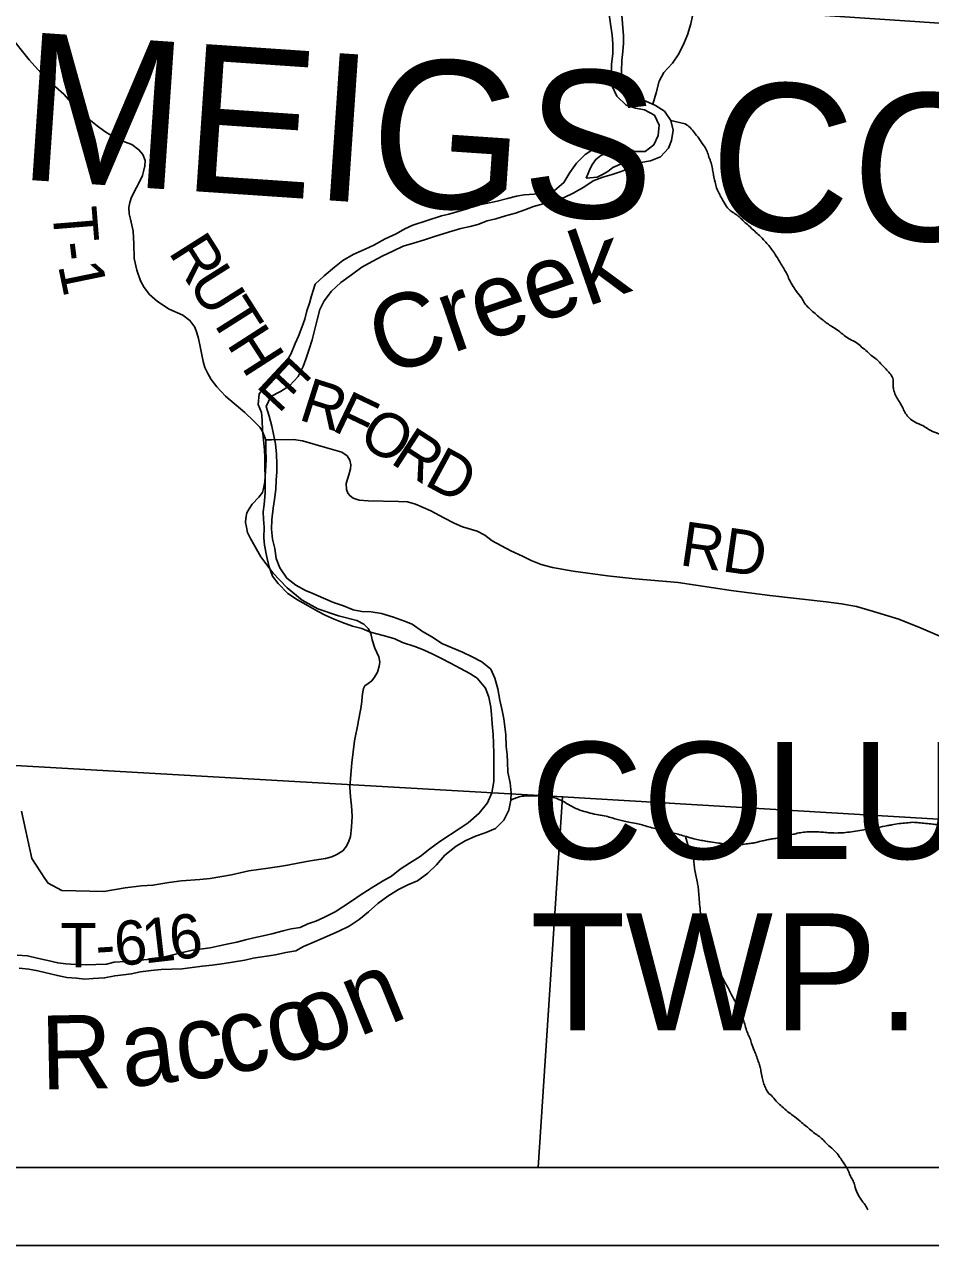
# Model space of a CAD drawing. Extents: x -8.2 to 34, y 0 to 22.
# Drawn here: x 4.523 to 5.685, y 14 to 15.567 of the extents above; entities that cross this region are included whole.
import ezdxf

# ---------------------------------------------------------------- set-up
doc = ezdxf.new("R2010")
doc.units = 0
for name, color, linetype in [('GM_X_Corporation', 7, 'Continuous'), ('GM_X_County_Text', 7, 'Continuous'), ('GM_X_Major_River', 7, 'Continuous'), ('GM_X_Major_River_Text', 7, 'Continuous'), ('GM_X_Minor_River', 7, 'Continuous'), ('GM_X_Township_Road', 7, 'Continuous'), ('GM_X_Township_Road_Text', 7, 'Continuous'), ('GM_X_Township_Text', 7, 'Continuous'), ('SH_Data', 7, 'Continuous')]:
    doc.layers.add(name, color=color, linetype=linetype)

msp = doc.modelspace()

# ---------------------------------------------------------------- linework, layer by layer
at = {"layer": 'GM_X_Corporation'}
for points in [[(4.1481, 14.1), (8.9, 14.1), (8.9, 15.3663), (8.5054, 15.392), (7.8479, 15.4343), (7.082, 15.4841), (6.7558, 15.5053), (6.7389, 15.5064), (6.2987, 15.5287), (5.4088, 15.5882), (4.4836, 15.6492), (4.4152, 15.6505), (4.2922, 15.6569), (4.2674, 15.658), (4.2558, 15.6585), (4.2352, 15.4906), (4.2113, 15.0848), (4.1846, 14.6878), (4.1741, 14.5315), (4.1604, 14.3288)], [(4.1538, 14.1), (5.1819, 14.1), (5.2132, 14.576), (4.1896, 14.6347)], [(5.1819, 14.1), (6.2054, 14.1), (6.2355, 14.5152), (5.2132, 14.576)]]:
    msp.add_lwpolyline(points, close=True, dxfattribs=at)
at = {"layer": 'GM_X_Major_River'}
for points in [[(5.272, 15.5853), (5.2766, 15.5533), (5.2778, 15.5423), (5.2778, 15.5298), (5.2759, 15.5157), (5.2756, 15.5017), (5.2768, 15.488), (5.2828, 15.4752), (5.2946, 15.4635), (5.3067, 15.4597), (5.3185, 15.4575), (5.331, 15.4507), (5.337, 15.4378), (5.3359, 15.4245), (5.3303, 15.4127), (5.319, 15.404), (5.3053, 15.4043), (5.294, 15.4104), (5.2807, 15.4141), (5.2674, 15.4141), (5.2557, 15.4091), (5.2421, 15.4004), (5.2312, 15.389), (5.2225, 15.3772), (5.2149, 15.3643), (5.2028, 15.354), (5.1904, 15.3513), (5.1767, 15.3494), (5.1639, 15.3486), (5.154, 15.3467), (5.1423, 15.3436), (5.1291, 15.3405), (5.1151, 15.3374), (5.1026, 15.3348), (5.0909, 15.3306), (5.0803, 15.3275), (5.0674, 15.3237), (5.0576, 15.3217), (5.0212, 15.3095), (5.0107, 15.3049), (4.9997, 15.2984), (4.9857, 15.292), (4.971, 15.284), (4.96, 15.2786), (4.9445, 15.2718), (4.9313, 15.2641), (4.9203, 15.2558), (4.9074, 15.2447), (4.8957, 15.2337), (4.8908, 15.2189), (4.8882, 15.2094), (4.8848, 15.1995), (4.8822, 15.1889), (4.8788, 15.1794), (4.8743, 15.1673), (4.8702, 15.1578), (4.8645, 15.1441), (4.8577, 15.1324), (4.8479, 15.1187), (4.8351, 15.1065), (4.8237, 15.0932), (4.8226, 15.0796), (4.8268, 15.0693), (4.8276, 15.0595), (4.828, 15.0466), (4.8292, 15.0337), (4.8307, 15.0212), (4.8311, 15.0113), (4.8311, 14.9988), (4.8315, 14.9863), (4.8316, 14.9659), (4.8301, 14.9511), (4.829, 14.9416), (4.8294, 14.9321), (4.8302, 14.9222), (4.8298, 14.9082), (4.8306, 14.8987), (4.8333, 14.8855), (4.8363, 14.8722), (4.8409, 14.8593), (4.8481, 14.8495), (4.8606, 14.8367), (4.8732, 14.8287), (4.8868, 14.8212), (4.8985, 14.8144), (4.9092, 14.8087), (4.9201, 14.8038), (4.9308, 14.7997), (4.9436, 14.7948), (4.9554, 14.7918), (4.9667, 14.7873), (4.9766, 14.7847), (4.9876, 14.7817), (4.9978, 14.7787), (5.0077, 14.7741), (5.0236, 14.7689), (5.0345, 14.7647), (5.0467, 14.7591), (5.0569, 14.7538), (5.0694, 14.7474)], [(5.2914, 15.5527), (5.2889, 15.5842)], [(5.1213, 14.7396), (5.1095, 14.749), (5.097, 14.7558), (5.0849, 14.7615), (5.0584, 14.7728), (5.0463, 14.7807), (5.0334, 14.7882), (5.0201, 14.7973), (5.0102, 14.8014), (4.9962, 14.8063), (4.9807, 14.8112), (4.9674, 14.8135), (4.9557, 14.8138), (4.9443, 14.8157), (4.9322, 14.8209), (4.9193, 14.8254), (4.9065, 14.8307), (4.8928, 14.8367), (4.8833, 14.8409), (4.8708, 14.8477), (4.8591, 14.8567), (4.8503, 14.87), (4.8458, 14.8817), (4.8439, 14.8946), (4.8408, 14.9067), (4.8396, 14.9196), (4.84, 14.9314), (4.8419, 14.9465), (4.8433, 14.9575), (4.8452, 14.9708), (4.8456, 14.9822), (4.8463, 14.9928), (4.8466, 15.003), (4.8459, 15.0159), (4.8447, 15.0288), (4.8401, 15.0516), (4.8367, 15.0644), (4.8329, 15.0769), (4.8389, 15.0895), (4.851, 15.0963), (4.8627, 15.1032), (4.8737, 15.1153), (4.8804, 15.1283), (4.8838, 15.1377), (4.888, 15.1506), (4.8917, 15.1624), (4.8981, 15.1882), (4.9015, 15.2015), (4.9071, 15.2125), (4.9166, 15.225), (4.9287, 15.2361), (4.9423, 15.246), (4.9555, 15.2555), (4.9687, 15.2631), (4.9823, 15.2703), (4.9963, 15.2768), (5.0088, 15.2825), (5.0217, 15.2864), (5.036, 15.2906), (5.0474, 15.2948), (5.061, 15.299), (5.0712, 15.3017), (5.0826, 15.3051), (5.0947, 15.3078), (5.1045, 15.3105), (5.1166, 15.3151), (5.1276, 15.3178), (5.1401, 15.3216), (5.1526, 15.325), (5.1647, 15.3292), (5.176, 15.3334), (5.1881, 15.3369), (5.2006, 15.3411), (5.215, 15.3453), (5.2267, 15.3507), (5.2403, 15.3583), (5.2524, 15.3663), (5.2649, 15.3712), (5.277, 15.3747), (5.2883, 15.3785), (5.3012, 15.3838), (5.3137, 15.3899), (5.3258, 15.3923), (5.3387, 15.3972), (5.3492, 15.4086), (5.353, 15.4181), (5.3549, 15.4314), (5.3522, 15.4439), (5.3438, 15.456), (5.3324, 15.4632), (5.3199, 15.4688), (5.3067, 15.4737), (5.2953, 15.4828), (5.2896, 15.4949), (5.2888, 15.5074), (5.2892, 15.5207), (5.2903, 15.5324), (5.2914, 15.5431), (5.2914, 15.5527)], [(5.2974, 15.3952), (5.2906, 15.3975), (5.2822, 15.4001), (5.2747, 15.402), (5.2686, 15.4016), (5.2622, 15.3989), (5.2558, 15.394), (5.2509, 15.3864), (5.2478, 15.3803), (5.2433, 15.37)], [(5.2433, 15.37), (5.2577, 15.3712), (5.2645, 15.3746), (5.2713, 15.3785), (5.2777, 15.3834), (5.2838, 15.3861), (5.2883, 15.3884), (5.2932, 15.3906), (5.2974, 15.3952)], [(5.0694, 14.7474), (5.0823, 14.7406), (5.094, 14.7342), (5.1035, 14.7282), (5.1142, 14.7153), (5.1187, 14.7039), (5.121, 14.6911), (5.1218, 14.6816), (5.123, 14.6695), (5.1241, 14.6558), (5.1245, 14.6448), (5.1249, 14.6312), (5.125, 14.5955), (5.1224, 14.5811), (5.1167, 14.5682), (5.1062, 14.5549), (5.0922, 14.5424), (5.0816, 14.5359), (5.0555, 14.5184), (5.0427, 14.5092), (5.0302, 14.4993), (5.0166, 14.4906), (5.0049, 14.483), (4.9935, 14.4742), (4.9822, 14.4677), (4.9675, 14.4586), (4.9535, 14.4498), (4.9436, 14.443), (4.9312, 14.4346), (4.9213, 14.4285), (4.9066, 14.4209), (4.8964, 14.4163), (4.8862, 14.4129), (4.8763, 14.4083), (4.865, 14.4064), (4.8548, 14.4041), (4.84, 14.3999), (4.829, 14.3976), (4.8169, 14.3949), (4.8063, 14.3926), (4.795, 14.3895), (4.7844, 14.3872), (4.7723, 14.3845), (4.7609, 14.3822), (4.7511, 14.381), (4.7382, 14.3791), (4.7273, 14.3764), (4.7114, 14.3726), (4.7008, 14.3703), (4.6909, 14.3687), (4.6803, 14.3672), (4.6667, 14.366), (4.6527, 14.3645), (4.6376, 14.3637), (4.6277, 14.3613), (4.6141, 14.3606), (4.6016, 14.3605), (4.5884, 14.3609), (4.5755, 14.3616), (4.5653, 14.3627), (4.5524, 14.3657), (4.5391, 14.3687), (4.5263, 14.3717), (4.5134, 14.3728)], [(4.5157, 14.3561), (4.5282, 14.3546), (4.5399, 14.3524), (4.5649, 14.3464), (4.5771, 14.3441), (4.5892, 14.343), (4.6001, 14.3419), (4.6107, 14.3427), (4.6255, 14.3435), (4.6387, 14.3462), (4.6497, 14.3474), (4.6596, 14.3486), (4.6717, 14.3512), (4.6853, 14.3532), (4.6982, 14.3543), (4.7114, 14.3548), (4.725, 14.3552), (4.7379, 14.3567), (4.7511, 14.3587), (4.7636, 14.3598), (4.7788, 14.3622), (4.792, 14.3641), (4.8053, 14.3664), (4.8159, 14.3687), (4.8446, 14.3733), (4.8579, 14.376), (4.8707, 14.3783), (4.8809, 14.3837), (4.8949, 14.3898), (4.9048, 14.394), (4.9252, 14.4031), (4.9392, 14.41), (4.952, 14.4184), (4.9641, 14.4283), (4.9762, 14.4389), (4.9891, 14.4484), (5.0027, 14.4568), (5.0144, 14.4629), (5.0272, 14.4683), (5.0401, 14.4781), (5.0514, 14.4888), (5.062, 14.501), (5.0764, 14.5124), (5.0881, 14.5196), (5.1013, 14.5253), (5.1138, 14.5299), (5.127, 14.5353), (5.1376, 14.5459), (5.1444, 14.5588), (5.1466, 14.5717), (5.147, 14.5812), (5.1458, 14.5937), (5.1428, 14.6077), (5.1424, 14.6206), (5.142, 14.6301), (5.1408, 14.6403), (5.1404, 14.6555), (5.1392, 14.6657), (5.1377, 14.6759), (5.1358, 14.6869), (5.1327, 14.6998), (5.1301, 14.7146), (5.1262, 14.7282), (5.1213, 14.7396)]]:
    msp.add_lwpolyline(points, dxfattribs=at)
at = {"layer": 'GM_X_Minor_River'}
for points in [[(5.3798, 15.5782), (5.3778, 15.5679), (5.3733, 15.5538), (5.3691, 15.5436), (5.3623, 15.5296), (5.3544, 15.5174), (5.343, 15.5056), (5.337, 15.4946), (5.3332, 15.4795), (5.3291, 15.4647)], [(5.3522, 15.4439), (5.3703, 15.4396)], [(5.3707, 14.5252), (5.3737, 14.5144)]]:
    msp.add_lwpolyline(points, dxfattribs=at)
for points in [[(5.3703, 15.4396), (5.3769, 15.4348), (5.3824, 15.4281), (5.3879, 15.4211), (5.394, 15.4122), (5.398, 15.406), (5.4004, 15.399), (5.4032, 15.3913), (5.4052, 15.3841), (5.4062, 15.3772), (5.4088, 15.3649), (5.4108, 15.3573), (5.414, 15.3503), (5.4172, 15.3445), (5.4222, 15.3356), (5.4281, 15.3286), (5.4344, 15.3242), (5.4399, 15.3202), (5.4462, 15.3139), (5.4517, 15.3092), (5.4598, 15.3017), (5.4657, 15.2962), (5.4727, 15.2891), (5.4778, 15.2833), (5.4826, 15.277), (5.4873, 15.27), (5.4934, 15.26), (5.4977, 15.253), (5.5009, 15.2472), (5.5041, 15.2398), (5.5091, 15.2309), (5.5135, 15.2243), (5.52, 15.2158), (5.5236, 15.2096), (5.5291, 15.2033), (5.5357, 15.1974), (5.542, 15.1919), (5.5475, 15.1875), (5.5587, 15.1795), (5.5668, 15.1743), (5.5746, 15.168), (5.582, 15.1632), (5.5899, 15.1591), (5.5965, 15.1536), (5.6043, 15.1469), (5.6102, 15.1417), (5.6165, 15.137), (5.6234, 15.1299), (5.6293, 15.1236), (5.6344, 15.1178), (5.6373, 15.1116), (5.6374, 15.1047), (5.638, 15.099), (5.6443, 15.0844), (5.6487, 15.0774), (5.6515, 15.0712), (5.6555, 15.065), (5.6613, 15.0595), (5.6703, 15.0546), (5.677, 15.0514), (5.6833, 15.0474), (5.6931, 15.0429), (5.6987, 15.0408), (5.7058, 15.0375), (5.7133, 15.035), (5.7211, 15.0309), (5.7275, 15.0281), (5.7346, 15.0252), (5.7421, 15.0219), (5.7496, 15.0178), (5.7577, 15.013), (5.7659, 15.0085), (5.7745, 15.0041), (5.7809, 15.0008), (5.7865, 14.998), (5.7936, 14.994), (5.7991, 14.9904), (5.8061, 14.9844), (5.812, 14.9789), (5.8215, 14.9664), (5.8284, 14.9582), (5.8328, 14.952), (5.8386, 14.945), (5.8426, 14.9391), (5.847, 14.9333), (5.852, 14.9255), (5.8556, 14.9197), (5.8592, 14.9131), (5.8635, 14.9062), (5.8686, 14.8988), (5.8714, 14.8926), (5.8761, 14.8845), (5.88, 14.8779), (5.8859, 14.8716), (5.8918, 14.8669), (5.8988, 14.8606)], [(5.1466, 14.5717), (5.1609, 14.5766), (5.1712, 14.577), (5.1807, 14.5774), (5.1872, 14.578), (5.1944, 14.5774), (5.2015, 14.5752), (5.2083, 14.5727), (5.2183, 14.5675), (5.2277, 14.5622), (5.2381, 14.5581), (5.2592, 14.5528), (5.269, 14.551), (5.2769, 14.5488), (5.2905, 14.5453), (5.298, 14.5435), (5.3078, 14.5417), (5.3154, 14.5399), (5.3236, 14.5374), (5.3319, 14.5352), (5.3394, 14.5331), (5.3481, 14.5305), (5.356, 14.5291), (5.3635, 14.5273), (5.3722, 14.5248), (5.3816, 14.5222), (5.3895, 14.5204), (5.397, 14.519), (5.4031, 14.518), (5.4133, 14.5166), (5.422, 14.5155), (5.4337, 14.5147), (5.4405, 14.5145), (5.4489, 14.5154), (5.4558, 14.5163), (5.4615, 14.5172), (5.4676, 14.5189), (5.4738, 14.5203), (5.4803, 14.5216), (5.4867, 14.5225), (5.4944, 14.5241), (5.5017, 14.5265), (5.5089, 14.5278), (5.5162, 14.5295), (5.5246, 14.5307), (5.533, 14.5312), (5.5421, 14.5309), (5.55, 14.5303), (5.5587, 14.5296), (5.569, 14.5296), (5.5789, 14.5304), (5.5892, 14.532), (5.5999, 14.5335), (5.6082, 14.5348), (5.6174, 14.5364), (5.63, 14.539), (5.6357, 14.54), (5.6449, 14.5415), (5.6544, 14.5424), (5.6628, 14.5432), (5.6704, 14.5426), (5.6791, 14.5419), (5.6878, 14.5409), (5.6938, 14.5403), (5.7006, 14.5393), (5.7063, 14.5384), (5.7127, 14.537), (5.7199, 14.5356), (5.7274, 14.5339), (5.7353, 14.5321), (5.7432, 14.5296), (5.7492, 14.5278), (5.7556, 14.5253), (5.7623, 14.5221), (5.7679, 14.5189), (5.7735, 14.5149), (5.7801, 14.5097), (5.7876, 14.5053), (5.7961, 14.4993), (5.8024, 14.4949), (5.8106, 14.4897), (5.8173, 14.4853), (5.8236, 14.4813), (5.8311, 14.4773), (5.8374, 14.4736), (5.8434, 14.4704), (5.8505, 14.4675), (5.8569, 14.465), (5.8666, 14.462), (5.8745, 14.4603), (5.8836, 14.4584), (5.8923, 14.4566), (5.9002, 14.4552), (5.9081, 14.4542), (5.9164, 14.4532), (5.924, 14.4525)], [(5.3737, 14.5144), (5.3777, 14.5094), (5.3809, 14.5009), (5.3817, 14.4918), (5.3826, 14.4838), (5.3842, 14.4754), (5.3858, 14.4673), (5.3871, 14.4608), (5.3877, 14.4544), (5.3885, 14.4441), (5.3896, 14.4326), (5.3908, 14.4212), (5.3928, 14.4128), (5.3951, 14.4047), (5.3987, 14.3966), (5.4007, 14.3886), (5.4034, 14.3794), (5.4097, 14.3625), (5.4136, 14.3532), (5.4175, 14.3455), (5.4218, 14.3374), (5.4253, 14.3312), (5.4282, 14.3254), (5.4321, 14.318), (5.436, 14.3103), (5.4392, 14.3026), (5.442, 14.2957), (5.4456, 14.288), (5.448, 14.2803), (5.4507, 14.2722), (5.4536, 14.266), (5.4556, 14.2595), (5.4591, 14.2503), (5.4616, 14.2441), (5.4643, 14.2364), (5.4664, 14.2303), (5.4677, 14.2242), (5.4693, 14.2158), (5.471, 14.2089), (5.4735, 14.2027), (5.4767, 14.1969), (5.4826, 14.191), (5.4888, 14.1836), (5.4947, 14.1785), (5.5024, 14.1717), (5.5087, 14.167), (5.518, 14.1595), (5.5246, 14.1539), (5.5302, 14.1496), (5.5368, 14.144), (5.5428, 14.14), (5.5483, 14.1349), (5.5549, 14.1282), (5.5623, 14.1215), (5.5681, 14.1145), (5.5721, 14.1087), (5.5768, 14.1013), (5.5803, 14.0947), (5.5828, 14.0889), (5.586, 14.0831), (5.5881, 14.0766), (5.5959, 14.0596), (5.6013, 14.0522), (5.6049, 14.046)]]:
    msp.add_spline(points, degree=3, dxfattribs=at)
at = {"layer": 'GM_X_Township_Road'}
for points in [[(4.5034, 15.5535), (4.5288, 15.5217), (4.5473, 15.5007), (4.5623, 15.487), (4.5731, 15.4776), (4.5887, 15.4601), (4.601, 15.4492), (4.6157, 15.4372), (4.6259, 15.4299), (4.6346, 15.4243), (4.6443, 15.4193), (4.6602, 15.413), (4.6695, 15.4063), (4.6745, 15.4001), (4.6775, 15.3927), (4.6769, 15.3856), (4.6755, 15.3784), (4.6739, 15.3732), (4.6706, 15.366), (4.6663, 15.3579), (4.66, 15.3455), (4.6579, 15.3388), (4.6566, 15.3321), (4.6568, 15.3241), (4.6586, 15.3174), (4.6619, 15.3019), (4.663, 15.2855), (4.6635, 15.2669), (4.6669, 15.2519), (4.6716, 15.238), (4.6762, 15.2295), (4.6831, 15.2207), (4.6934, 15.2115), (4.7082, 15.2018), (4.7259, 15.194), (4.735, 15.1873), (4.7412, 15.1788), (4.744, 15.1716), (4.7458, 15.1643), (4.7481, 15.1537), (4.752, 15.1348), (4.7541, 15.1267), (4.7578, 15.119), (4.7621, 15.1115), (4.7695, 15.1022), (4.7804, 15.0903), (4.8053, 15.069), (4.8164, 15.0586), (4.8246, 15.0503), (4.8274, 15.0467), (4.8288, 15.0427), (4.8325, 15.0342), (4.8398, 15.0339), (4.868, 15.0345), (4.8795, 15.0327), (4.9091, 15.0243), (4.9299, 15.0184), (4.9367, 15.0136), (4.9401, 15.0079), (4.9414, 15.0019), (4.9411, 14.9968), (4.9387, 14.9892), (4.9353, 14.9782), (4.9358, 14.9704), (4.9376, 14.9655), (4.9404, 14.9621), (4.9444, 14.9593), (4.9523, 14.9566), (4.9636, 14.9556), (5.0024, 14.9549), (5.014, 14.9546), (5.0245, 14.9515), (5.0439, 14.943), (5.0609, 14.934), (5.0739, 14.9273), (5.0848, 14.9226), (5.1034, 14.9168), (5.1136, 14.9119), (5.1229, 14.9045), (5.1466, 14.8918), (5.1616, 14.8847), (5.173, 14.8791), (5.1857, 14.8742), (5.2003, 14.8702), (5.2269, 14.8656), (5.2708, 14.8597), (5.3062, 14.8558), (5.3613, 14.851), (5.4293, 14.8406), (5.479, 14.8341), (5.5515, 14.8262), (5.5709, 14.8238), (5.5904, 14.8201), (5.6121, 14.8137), (5.6445, 14.8039), (5.6733, 14.7925), (5.7182, 14.7732)], [(4.5489, 14.4713), (4.5531, 14.4649), (4.5704, 14.4555), (4.6245, 14.4544), (4.6519, 14.459), (4.6729, 14.4617), (4.6874, 14.4624), (4.708, 14.4659), (4.7241, 14.4682), (4.7476, 14.47), (4.7608, 14.4712), (4.7882, 14.4758), (4.8106, 14.4808), (4.8355, 14.4843), (4.8555, 14.4875), (4.8894, 14.4938), (4.9088, 14.4967), (4.9169, 14.4988), (4.9233, 14.5018), (4.9311, 14.5067), (4.9358, 14.5125), (4.939, 14.5191), (4.9409, 14.5251), (4.9425, 14.5371), (4.9432, 14.5512), (4.9425, 14.5643), (4.9409, 14.5761), (4.9402, 14.5883), (4.9413, 14.6044), (4.9427, 14.6197), (4.9461, 14.6476), (4.9507, 14.6709), (4.9508, 14.6717), (4.9544, 14.6893), (4.9554, 14.6981), (4.9558, 14.7047), (4.9567, 14.7107), (4.9575, 14.7149), (4.9595, 14.7183), (4.9635, 14.7214), (4.9685, 14.7248), (4.9718, 14.7294), (4.9756, 14.7359), (4.9778, 14.7435), (4.9786, 14.7488), (4.9775, 14.7554), (4.9724, 14.7668), (4.9687, 14.7774), (4.9669, 14.7856), (4.9635, 14.7919), (4.9581, 14.7974), (4.9491, 14.8022), (4.9258, 14.8083), (4.8993, 14.8172), (4.8791, 14.8283), (4.8599, 14.8442), (4.8415, 14.8633), (4.8258, 14.8841), (4.8127, 14.9074), (4.809, 14.915), (4.8074, 14.9221), (4.8064, 14.9281), (4.8069, 14.9337), (4.808, 14.9404), (4.811, 14.9457), (4.8149, 14.9515), (4.8235, 14.9606), (4.8279, 14.9667), (4.8295, 14.9718), (4.8309, 14.98), (4.832, 14.9937), (4.8327, 15.0084), (4.8325, 15.0218), (4.8325, 15.0342)], [(4.519, 14.5574), (4.5319, 14.4968), (4.5489, 14.4713)]]:
    msp.add_lwpolyline(points, dxfattribs=at)
at = {"layer": 'SH_Data'}
for p, q in [((4.1481, 14.1), (8.9, 14.1)), ((2, 14), (9, 14))]:
    msp.add_line(p, q, dxfattribs=at)

# ---------------------------------------------------------------- texts
at = {"layer": 'GM_X_County_Text'}
msp.add_text('MEIGS COUNTY', height=0.189394, rotation=356.1113, dxfattribs=at).set_placement((4.512, 15.3687))
at = {"layer": 'GM_X_Major_River_Text'}
for s, height, rotation, p in [('Creek', 0.0947, 19.0988, (4.9848, 15.115)), ('on', 0.09469, 22.0989, (4.8864, 14.241)), ('co', 0.0947, 13.1008, (4.781, 14.2175)), ('R', 0.0947, 1.1029, (4.5442, 14.2003)), ('ac', 0.0947, 7.102, (4.6511, 14.2023))]:
    msp.add_text(s, height=height, rotation=rotation, dxfattribs=at).set_placement(p)
at = {"layer": 'GM_X_Township_Road_Text'}
for s, height, rotation, p in [('T', 0.0568, 274.6248, (4.5582, 15.331)), ('R', 0.0568, 302.319, (4.7065, 15.275)), ('-', 0.0568, 276.9198, (4.5619, 15.2862)), ('1', 0.0568, 281.6376, (4.5655, 15.258)), ('U', 0.0568, 302.3208, (4.7315, 15.2356)), ('T', 0.0568, 302.3207, (4.7582, 15.1933)), ('H', 0.0568, 302.7166, (4.7812, 15.1571)), ('E', 0.0568, 317.0494, (4.8181, 15.1031)), ('R', 0.0568, 342.3324, (4.8727, 15.0605)), ('F', 0.0568, 334.5123, (4.9152, 15.0471)), ('O', 0.0568, 328.0894, (4.9484, 15.0314)), ('R', 0.0568, 327.0439, (4.9906, 15.0051)), ('D', 0.0568, 331.5761, (5.0339, 14.9772)), ('RD', 0.05682, 351.7984, (5.362, 14.8735)), ('6', 0.0568, 5.1433, (4.6402, 14.3587)), ('1', 0.0568, 6.5284, (4.6765, 14.362)), ('6', 0.0568, 6.8816, (4.7117, 14.366)), ('T', 0.0568, 359.9957, (4.5688, 14.357)), ('-', 0.0568, 3.7069, (4.6153, 14.3571))]:
    msp.add_text(s, height=height, rotation=rotation, dxfattribs=at).set_placement(p)
at = {"layer": 'GM_X_Township_Text'}
for s, p in [('COLUMBIA', (5.1714, 14.4963)), ('TWP.', (5.1714, 14.2763))]:
    msp.add_text(s, height=0.15, rotation=0, dxfattribs=at).set_placement(p)

doc.saveas('drawing.dxf')
